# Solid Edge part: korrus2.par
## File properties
Author: Indrek
Template: Normal.par
Last saved by: Indrek
Revision: 13
Application: Solid Edge
Density: 7750,000 kg/m^3
Accuracy: 0,990
Material: Stainless Steel, 420
Face Style: Steel
Fill Style: ANSI32(Steel)
Virtual Style: Stainless steel
Coef. of Thermal Exp: 1e-05
Thermal Conductivity: 25.0
Specific Heat: 502.0
Modulus of Elasticity: 19994795300.0
Poission's Ratio: 0.29
Yield Stress: 344737850.0
Ultimate Stress: 655001915.0
Elongation: 0.0
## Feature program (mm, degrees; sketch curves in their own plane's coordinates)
make body feature "unnamed MakeBodyFeature 1"
sketch for "ExtrudedProtrusion_1" plane through (0, -392.2606, -246.4564) normal (0, -1, 0) x-axis (1, 0, 0)
  line (-90.7432, 47.25) -> (90.7431, 47.25)
extrude "ExtrudedProtrusion_1" add finite 189.0147 along +normal
sketch for "ExtrudedCutout_3" plane through (0, -290.6352, -199.2064) normal (0, 0, 1) x-axis (-1, 0, 0)
  line (145.5469, 330.1731) -> (178.3941, 235.8643)
  line (178.3941, 235.8643) -> (98.2107, 226.7853)
  line (-160.2715, 235.8643) -> (-98.1997, 222.207)
  line (-160.2715, 235.8643) -> (-57, 370.9489)
  line (-57, 370.9489) -> (145.5469, 330.1731)
extrude "ExtrudedCutout_3" cut finite 101.9235 along -normal
fillet "Round_2" radius 10
sketch for "ExtrudedCutout_4" plane through (0, 0, -246.4564) normal (0, 1, 0) x-axis (-1, 0, 0)
  line (273.4104, -26.8609) -> (-272.8495, -26.8609)
  line (-272.8495, -26.8609) -> (-272.8495, -55.6215)
  line (-272.8495, -55.6215) -> (273.4104, -55.6215)
  line (273.4104, -55.6215) -> (273.4104, -26.8609)
extrude "ExtrudedCutout_4" cut finite 586.9261 along -normal
sketch for "ExtrudedCutout_5" plane through (0.0001, 0, -236.2639) normal (0, 1, 0) x-axis (-1, 0, 0)
  line (253.7718, -2.0535) -> (-252.6501, -2.0535)
  line (-252.6501, -2.0535) -> (-252.6501, 46.8306)
  line (-252.6501, 46.8306) -> (253.7718, 46.8306)
  line (253.7718, 46.8306) -> (253.7718, -2.0535)
extrude "ExtrudedCutout_5" cut finite 595.3607 along -normal
thinwall "Thinwall_10"  Thickness = 4 mm
sketch for "unnamed Cutout 1" plane through (90.7431, -635.3625, -199.2064) normal (0, -1, 0) x-axis (-1, 0, 0)
  line (90.7391, 42.4898) -> (162.1168, 42.4898)
  line (162.1168, 42.4898) -> (162.1168, 60.9493)
  line (162.1168, 60.9493) -> (90.7391, 60.9493)
  line (19.3615, 60.9493) -> (90.7391, 60.9493)
  line (19.3615, 42.4898) -> (19.3615, 60.9493)
  line (90.7391, 42.4898) -> (19.3615, 42.4898)
extrude "unnamed Cutout 1" cut along -normal
sketch for "ExtrudedCutout_8" plane through (0, -290.6376, -238.2674) normal (0, 0, 1) x-axis (0, 1, 0)
  line (-258.4186, 71.3737) -> (-263.8561, 71.3737)
  arc centre (-184.616, 0.935) radius 106.0217 from (-263.8561, 71.3737) to (-262.1459, -71.3817) ccw
  line (-256.5793, -71.3817) -> (-262.1459, -71.3817)
  arc centre (-184.616, 0.935) radius 102.0217 from (-258.4186, 71.3737) to (-256.5793, -71.3817) ccw
extrude "ExtrudedCutout_8" cut finite 20.9565 along -normal
Other named dimensions: "OffsetSurface_5": Distance = 0.05 mm | "OffsetSurface_7": Distance = 0.05 mm | "OffsetSurface_8": Distance = 3.175 mm | "OffsetSurface_9": Distance = 4 mm
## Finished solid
Body 1: sheet body, 1 face, 4 edges, 4 vertices.
  Faces by surface: cylinder 1
  Edges by curve: circle 2, curve on surface 2
Body 2: sheet body, 1 face, 4 edges, 4 vertices.
  Faces by surface: cylinder 1
  Edges by curve: circle 2, curve on surface 2
Body 3: sheet body, 1 face, 16 edges, 16 vertices.
  Faces by surface: plane 1
  Edges by curve: curve on surface 8, line 6, circle 2
Body 4: sheet body, 1 face, 16 edges, 16 vertices.
  Faces by surface: plane 1
  Edges by curve: curve on surface 8, line 6, circle 2
Body 5: solid body, 23 faces, 63 edges, 42 vertices.
  Faces by surface: plane 9, blend 4, offset 4, cylinder 2, spline 2, swept 2
  Edges by curve: intersection 28, line 21, circle 10, curve on surface 2, ellipse 2
Body 6: solid body, 4 faces, 6 edges, 4 vertices.
  Faces by surface: plane 3, spline 1
  Edges by curve: line 2, spline 2, curve on surface 1, ellipse 1
Bounding box of the edges (mm; curved faces can reach further): 437.086 x 584.450 x 94.500, from (-218.5431, -584.4503, -293.7064) to (218.5431, 0, -199.2064).
Cylindrical faces by radius (mm): R102.0217 x2, R106.0217 x1, R109.1967 x1
Planar faces by outward normal: +x 1, +y 3, +z 5, -x 1, -y 1, -z 1
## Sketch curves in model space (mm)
line (-71.3737, -635.3625, -241.6962) -> (-71.3737, -635.3625, -260.1557)
line (-71.3737, -635.3625, -260.1557) -> (0.004, -635.3625, -260.1557)
line (71.3817, -635.3625, -260.1557) -> (0.004, -635.3625, -260.1557)
line (71.3817, -635.3625, -241.6962) -> (71.3817, -635.3625, -260.1557)
line (0.004, -635.3625, -241.6962) -> (71.3817, -635.3625, -241.6962)
line (0.004, -635.3625, -241.6962) -> (-71.3737, -635.3625, -241.6962)
line (-92.2487, -395.3119, -238.3174) -> (92.2548, -395.3119, -238.3174)
line (92.2548, -395.3119, -238.3174) -> (92.2548, -391.3119, -238.3174)
line (92.2548, -391.3119, -238.3174) -> (-92.2487, -391.3119, -238.3174)
line (-92.2487, -391.3119, -238.3174) -> (-92.2487, -395.3119, -238.3174)
ellipse centre (0, -392.2606, -225.3386) radii 98.1997, 68.3678 from (0.0062, -392.2606, -293.7064) through (83.2252, -392.2606, -261.6269) to (90.7431, -392.2606, -199.2064)
ellipse centre (0, -392.2606, -225.3386) radii 98.1997, 68.3678 from (-90.7431, -392.2606, -199.2064) through (5.838, -392.2606, -293.5855) to (90.7431, -392.2606, -199.2064)
line (-90.7431, -392.2606, -199.2064) -> (90.7431, -392.2606, -199.2064)
line (44.3041, -171.7493, -199.2064) -> (181.7265, -171.7493, -199.2064)
ellipse centre (0, -171.7493, -225.3386) radii 196.6594, 68.3678 from (-181.7265, -171.7493, -199.2064) through (11.6914, -171.7493, -293.5855) to (181.7265, -171.7493, -199.2064)
line (-181.7265, -171.7493, -199.2064) -> (181.7265, -171.7493, -199.2064)
ellipse centre (0, 0, -225.3386) radii 218.5431, 68.3678 from (-201.9485, 0, -199.2064) through (12.9924, 0, -293.5855) to (201.9485, 0, -199.2064)
line (201.9485, 0, -199.2064) -> (-201.9485, 0, -199.2064)
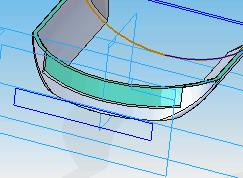
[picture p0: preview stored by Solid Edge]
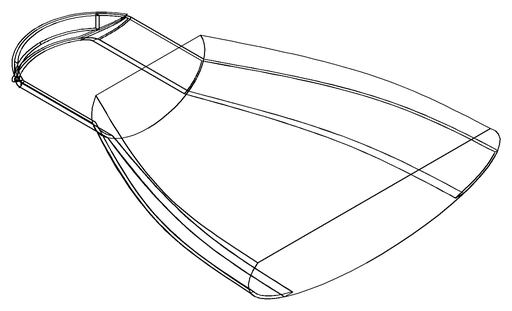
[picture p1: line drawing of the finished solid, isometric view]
